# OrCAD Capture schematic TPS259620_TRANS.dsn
size Custom; title: TPS25962x 2.7 V - 19 V, 2 A  eFuse; rev: 1.0; note: SLVSET8A- Aug 2019
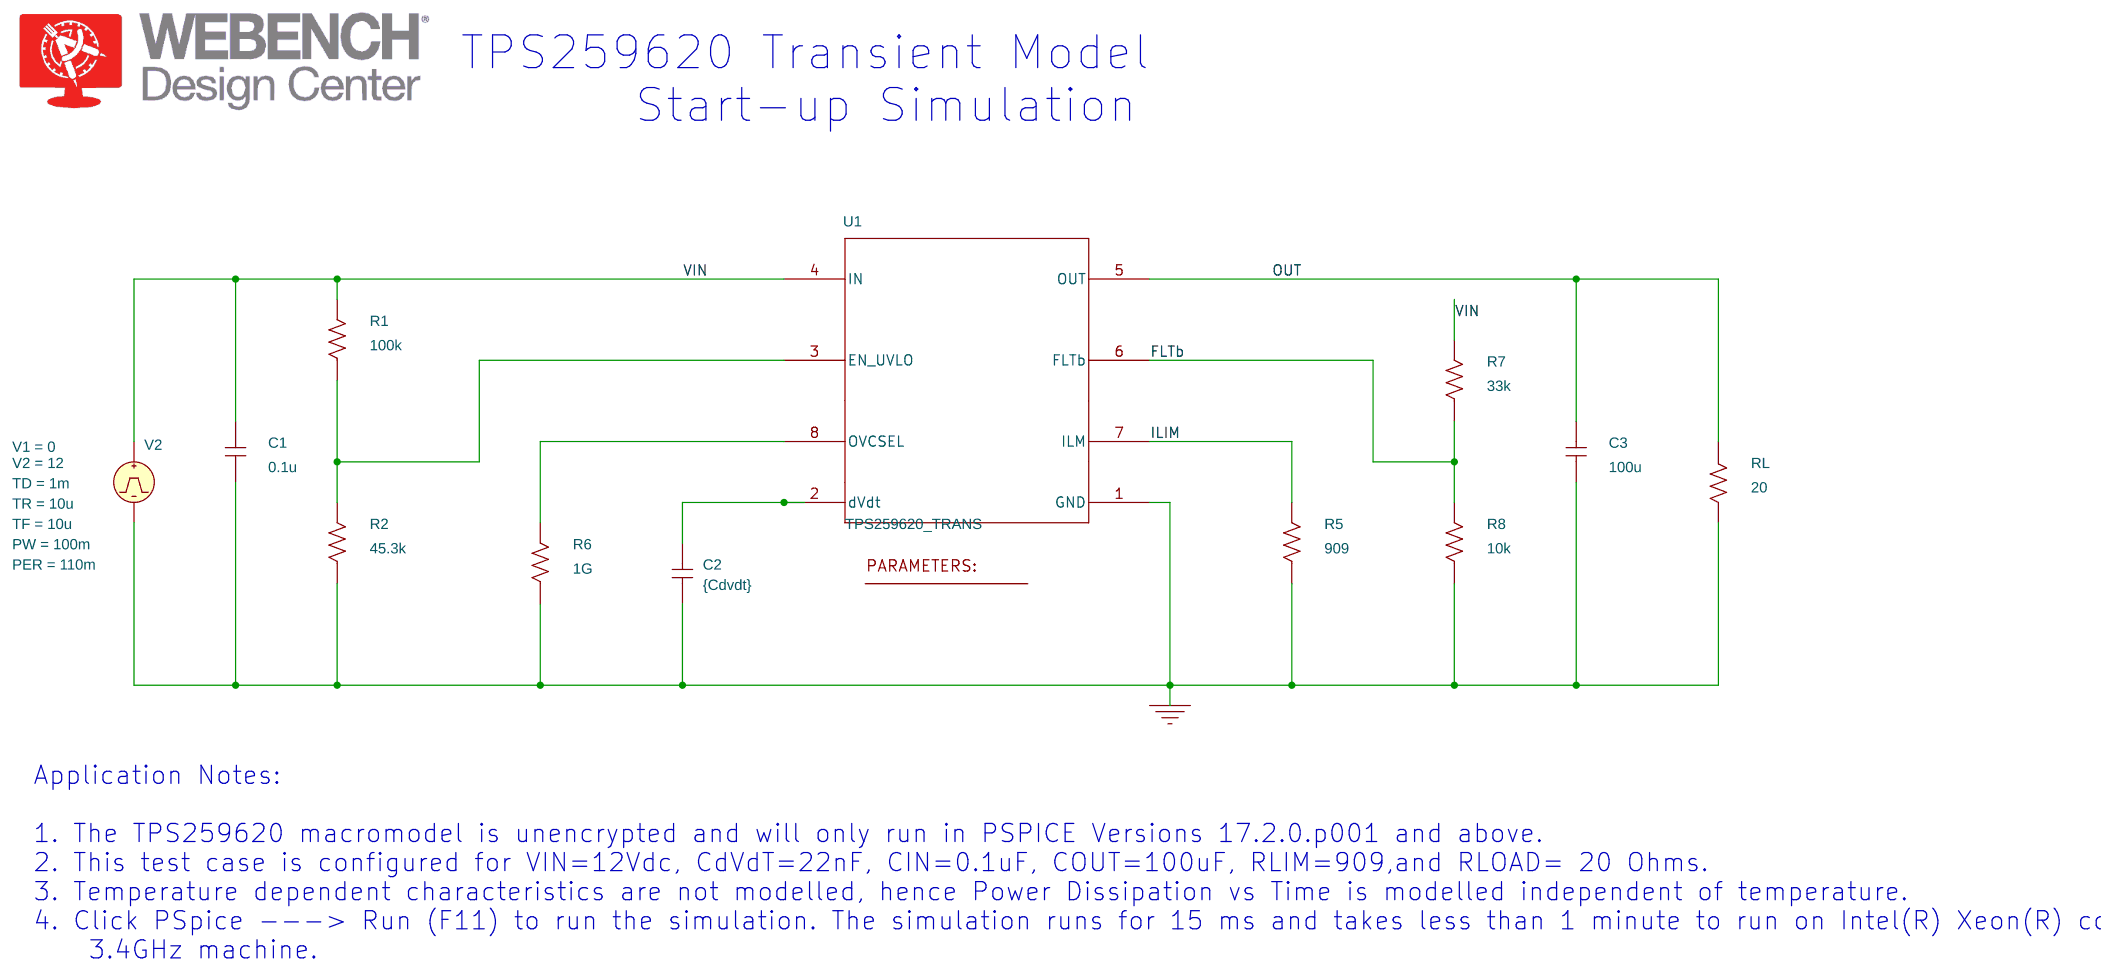
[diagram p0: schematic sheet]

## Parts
1  PARAM
C1  0.1u  [RAD/CK05]
C2  {Cdvdt}  [RAD/CK05]
C3  100u  [RAD/CK05]
R1  100k  [AX/RC05]
R2  45.3k  [AX/RC05]
R5  909  [AX/RC05]
R6  1G  [AX/RC05]
R7  33k  [AX/RC05]
R8  10k  [AX/RC05]
RL  20  [AX/RC05]
U1  TPS259620_TRANS  [DRC0010J]
V2  VPULSE

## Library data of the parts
1 = PARAM: Cdvdt: 22n
C1-C3 = C
R1 R2 R5-R8 RL = R
U1 = TPS259620_TRANS
V2 = VPULSE: PER: 110m; PW: 100m; TD: 1m; TF: 10u; TR: 10u; V1: 0; V2: 12

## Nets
VIN: C1.1 R1.2 R7.2 U1.4(IN) V2.1(+)
0: C1.2 C2.2 C3.2 R2.1 R5.1 R6.1 R8.1 RL.2 U1.1(GND) V2.2(-)
FLTb: R7.1 R8.2 U1.6(FLTb)
ILIM: R5.2 U1.7(ILM)
OUT: C3.1 RL.1 U1.5(OUT)
N16818341: R1.1 R2.2 U1.3(EN_UVLO)
N16818581: C2.1 U1.2(dVdt)
N16848724: R6.2 U1.8(OVCSEL)

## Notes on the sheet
- TPS259620 Transient Model
         Start-up Simulation
- Application Notes:
  1. The TPS259620 macromodel is unencrypted and will only run in PSPICE Versions 17.2.0.p001 and above.
  2. This test case is configured for VIN=12Vdc, CdVdT=22nF, CIN=0.1uF, COUT=100uF, RLIM=909,and RLOAD= 20 Ohms.
  3. Temperature dependent characteristics are not modelled, hence Power Dissipation vs Time is modelled independent of temperature.
  4. Click PSpice ---> Run (F11) to run the simulation. The simulation runs for 15 ms and takes less than 1 minute to run on Intel(R) Xeon(R) core,
      3.4GHz machine.
